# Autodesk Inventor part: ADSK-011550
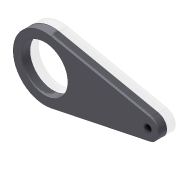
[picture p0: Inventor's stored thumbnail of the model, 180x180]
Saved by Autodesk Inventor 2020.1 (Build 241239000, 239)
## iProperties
Created: 2000-02
Part Number: ADSK-011550
Material: Pearson HRS
Document SubType Name: Modeling
Designer: glanglot
Density: 7.83 g/cm^3
Appearance: Métal - Acier
Mass: 3930.53 g
Surface Area: 744.66 cm^2
Volume: 501.984 cm^3
Control State: 0
Checked Out: False
Master: False
Shininess: 0.0
Length Units: 11269
Angle Units: 11279
Time Units: 11290
Mass Units: 11283
Length Display Precision: 3
Angle Display Precision: 2
Compacted: True
Cutlength: 14
Material Desc: FLAT,CRS,0.750X06.000
Material_Number: A091127
Dimensions: 345x150x20 mm
Mass: 3,931 kg
Density: 0.0
Volumn: 0.0
Area: 0.0
PropertySet Name: Model Information
Author: glanglot
Revision Number: -
Title: ADSK-011550
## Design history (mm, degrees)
node "Solide1"
  node "Extrusion2" dims "d7" = 20, "d8" = 0
sketch "Sketch1"
  geometry: L1 (-144, 0)-(339, 0) reference; L2 (15.306, 73.422)-(250.102, 24.474); L3 (250.102, -24.474)-(15.306, -73.422); C1 r 55 at (0, 0); C2 r 8.5 at (245, 0); A1 r 75 centre (0, 0) between (15.306, 73.422) and (15.306, -73.422); A2 r 25 centre (245, 0) between (250.102, -24.474) and (250.102, 24.474); 1 further point
  constraints: 4 centre point, 4 end point, 4 point on circle, 4 tangent, 3 coincident, 1 point on line
  dimensions: "d0" = 150 diameter of A1; "d1" = 50 diameter of A2; "d2" = 245 distance of A2.centre A1.centre; "d5" = 110 diameter of C1; "d6" = 17 diameter of C2
node "Corps solides"
node "Corps surfaciques"
